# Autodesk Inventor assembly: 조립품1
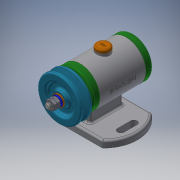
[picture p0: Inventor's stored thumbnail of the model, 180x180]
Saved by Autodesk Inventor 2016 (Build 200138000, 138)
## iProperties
Created: 2021-09
Part Number: 조립품1
Material: 일반
Document SubType Name: Weldment
Designer: pc-04
Weld Material: Welded Aluminum-6061
Author: pc-04
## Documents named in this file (13)
- C:\Users\pc-04\Desktop\710906V1026\조립품1.iam
- C:\Users\pc-04\Desktop\710906V1026\본체.ipt
- C:\Users\pc-04\Desktop\710906V1026\앞커버.ipt
- C:\Users\pc-04\Desktop\710906V1026\뒤커버.ipt
- C:\Users\pc-04\Desktop\710906V1026\베어링 15x32x9.ipt
- C:\Users\pc-04\Desktop\710906V1026\축.ipt
- C:\Users\pc-04\Desktop\710906V1026\캡.ipt
- C:\Users\pc-04\Desktop\710906V1026\키 3x3.ipt
- C:\Users\pc-04\Desktop\710906V1026\V벨트풀리.ipt
- C:\Users\pc-04\Desktop\710906V1026\와셔 8x17.ipt
- C:\Users\pc-04\Desktop\710906V1026\스프링와셔 8.ipt
- C:\Users\pc-04\Desktop\710906V1026\너트 M8.ipt
- C:\Users\pc-04\Desktop\710906V1026\볼트 M4x12.ipt
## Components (1 placed, 1 different names)
1. V벨트풀리:1
